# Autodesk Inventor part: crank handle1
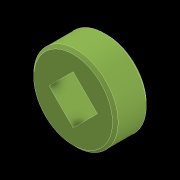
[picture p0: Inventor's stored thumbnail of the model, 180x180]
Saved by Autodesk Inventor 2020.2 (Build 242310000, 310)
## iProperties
Category: 11
Manager: PART
Company: 21
Created: 2020-10
Part Number: crank handle1
Material: Generic
Document SubType Name: Modeling
Designer: Apardo
Density: 1 g/cm^3
Appearance: Olive Green
Vendor: 11
Project: PLATE ROLLING MACHINE
Cost Center: 1
Engineer: STEEL C45
Stock Number: 2.1
Description: crank handle1
Engr Approved By: D. JAEGER
Author: Apardo
Revision Number: 1.0
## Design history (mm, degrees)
sketch "Sketch1"
  geometry: L1 (-8.627, 0)-(0, 8.627); L2 (0, 8.627)-(8.627, 0); L3 (8.627, 0)-(0, -8.627); L4 (0, -8.627)-(-8.627, 0); L5 (-8.627, 0)-(8.627, 0); L6 (0, 8.627)-(0, -8.627); C1 r 15 at (0, 0); 2 further points
  constraints: 12 end point, 3 midpoint, 2 parallel, 2 perpendicular, 1 centre point, 1 coincident, 1 vertical alignment
  dimensions: "d0" = 30 diameter of C1; "d1" = 12.2 distance of L1.end L2.end
extrude "Extrusion1" new body sketch "Sketch1" stored distance "d2" = 12; taper "d3" = 0 deg
chamfer "Chamfer1" distance "d4" = 1; stored, may be unused: second distance "d5" = 2, angle "d6" = 45 deg
body "Solid1"
